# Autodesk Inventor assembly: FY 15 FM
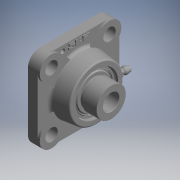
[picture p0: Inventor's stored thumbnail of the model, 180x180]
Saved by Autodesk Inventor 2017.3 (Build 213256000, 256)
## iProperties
Category: PARTsolutions
Company: SKF
Part Number: FY 15 FM
Catalog Web Link: www.cadenas.de
Description: AYF_001HC_HH_HY-Y-bearing square flanged units
Vendor: SKF
Document SubType Name: Assembly
Designer: partserver
Manufacturer: SKF
Mass: 400 g
Surface Area: 332.086 cm^2
Volume: 55.8843 cm^3
Density: 7.15765 g/cm^3
Title: FY 15 FM
Author: Cadenas PARTsolutions
Comments: Y-bearing square flanged units
PSOL_IDENT_0: {$CADENAS_DATA\23d-libs\skf\bearings_units_and_housings\bearing_units\ball_bearing_units\y-units\ayf
PSOL_IDENT_1: _001hc_hh_hy.prj},187 {VTYP=3D},{STYP=ASSTAB},{NB=FY 15 FM},{LINA=FY 15 FM},{NN=AYF_001HC_HH_HY},{DA
PSOL_IDENT_2: TE=20.08.2020 12:22:38},{GEOMDATE=20.08.2020 12:22:32},{VERSION=},{LINEID=52770},{WBVAR=COVER},{WBNU
PSOL_IDENT_3: MERIC=}  {NB=FY 15 FM},{LINA=FY 15 FM},{KT=DUMMY},{DESIGNATION=FY 15 FM},{HOUSING=FY 503 M},{BEARING=
PSOL_IDENT_4: YET 203/15},{COVER=},{DD=15},{DDX=},{DDALG=15.000},{DD1=24.200},{DD2=27.200},{DD3=},{AALG=26.000},{A=
PSOL_IDENT_5: 26},{AX=},{AXX=},{A1ALG=11.000},{A1=11},{A1X=},{A1XX=},{A3ALG=3.200},{A3=3.2},{A3X=},{A5ALG=0.000},{
PSOL_IDENT_6: A5=},{A5X=},{A5XX=},{B=MIN},{B1=28.600},{B1X=},{B4ALG=4.750},{B4=},{B4X=4.75},{DAAALG=55.600},{DAA=5
PSOL_IDENT_7: 5.6},{DAAX=},{DB=MIN},{DB1=50.000},{DB1X=},{DB2=53.000},{DB2X=},{HA=},{J=54.000},{JX=},{JXX=},{L=76.
PSOL_IDENT_8: 000},{LX=},{LXX=},{N=11.500},{NX=},{NXX=},{SS1=22.100},{SS1X=},{T=39.600},{TX=},{DN=6.500},{SWN=7},{
PSOL_IDENT_9: GN=1/4-28 SAE-LT},{RG=1/4-28 UNF},{RGX=},{R1=19},{R1X=},{J6=66},{J7=14.500},{N4=4},{D=40.000},{C=12.
PSOL_IDENT_10: 000},{R12=0.300},{DW=6.747},{B3=13.500},{PITCH=28.500},{LOAD1=9.560},{LOAD2=4.750},{LOAD3=0.200},{SP
PSOL_IDENT_11: EED1=9500},{II=1},{Z=8},{MASS=0.400},{MASSX=},{G2=M6x0.75},{HKSGS=3},{RTTGS=4},{ALPHA=},{GALG=10.000
PSOL_IDENT_12: },{G=10},{GX=},{GXX=},{GINALG=0.375},{GIN=0.375000002475},{GINX=},{GINXX=},{EC=},{BS=},{SLEEVE=},{PO
PSOL_IDENT_13: PULAR=},{D1=MIN},{K=1.3},{CC1=3.6},{BRGTYP=BBY_005},{COVERALG=  '', 'No end cover' },{SUPPRESSED=uns
PSOL_IDENT_14: uppressed},{TC=FY 15 FM},{PPATH=y-bearing_square_flanged_units_parts/ayf_001hc_hh_hy_asmtpl.prj}
NB: FY 15 FM
NN: AYF_001HC_HH_HY
NT: Y-bearing square flanged units
NBSYN: $TC.
LINA: FY 15 FM
CATALOG: SKF
DESIGNATION: FY 15 FM
HOUSING: FY 503 M
BEARING: YET 203/15
COVER: No end cover
DDALG: 15
J: 54
L: 76
T: 39.6
LOAD1: 9.56
LOAD2: 4.75
SPEED1: 9500
SUPPLIER: SKF
ARTICLENO: FY 15 FM
BOMINFO: FY 15 FM
CREATOR: CADENAS GmbH
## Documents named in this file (6)
- e:\temp\worker_102\temp\exporttempdir_144_257_MNU6y\format_0\FY 15 FM.iam
- e:\temp\worker_102\temp\exporttempdir_144_257_MNU6y\format_0\FY 15 FM0_375000002475-dummy.ipt
- e:\temp\worker_102\temp\exporttempdir_144_257_MNU6y\format_0\FY 503 M-housing.ipt
- e:\temp\worker_102\temp\exporttempdir_144_257_MNU6y\format_0\1_4-28 SAE-LT.ipt
- e:\temp\worker_102\temp\exporttempdir_144_257_MNU6y\format_0\YET 203_15-24_21030112021228_6-bearing.ipt
- e:\temp\worker_102\temp\exporttempdir_144_257_MNU6y\format_0\15-40-19_1-12-ybrg2-124-6_747-28_5.ipt
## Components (12 placed, 5 different names)
1. FY 15 FM0_375000002475-dummy:1 — brg_XY@1 <-> housing_XY@2, brg_Z@1 <-> housing_Z@2, brg_YZ@1 <-> housing_YZ@2
2. FY 503 M-housing:1 — brg_XY@1 <-> housing_XY@2, brg_Z@1 <-> housing_Z@2, brg_YZ@1 <-> housing_YZ@2, gn_XY@2 <-> gn_XY@3, gn_Z@2 <-> gn_Z@3, gn_YZ@2 <-> gn_YZ@3, housing_XY@2 <-> brg3_XY@4, housing_Z@2 <-> brg3_Z@4, housing_YZ@2 <-> brg3_YZ@4
3. 1_4-28 SAE-LT:1 — gn_XY@2 <-> gn_XY@3, gn_Z@2 <-> gn_Z@3, gn_YZ@2 <-> gn_YZ@3
4. YET 203_15-24_21030112021228_6-bearing:1 — housing_XY@2 <-> brg3_XY@4, housing_Z@2 <-> brg3_Z@4, housing_YZ@2 <-> brg3_YZ@4, ball_1_XY@4 <-> ball_XY@5, ball_1_Z@4 <-> ball_Z@5, ball_1_YZ@4 <-> ball_YZ@5, ball_2_XY@4 <-> ball_XY@6, ball_2_Z@4 <-> ball_Z@6, ball_2_YZ@4 <-> ball_YZ@6, ball_3_XY@4 <-> ball_XY@7, ball_3_Z@4 <-> ball_Z@7, ball_3_YZ@4 <-> ball_YZ@7, ball_4_XY@4 <-> ball_XY@8, ball_4_Z@4 <-> ball_Z@8, ball_4_YZ@4 <-> ball_YZ@8, ball_5_XY@4 <-> ball_XY@9, ball_5_Z@4 <-> ball_Z@9, ball_5_YZ@4 <-> ball_YZ@9, ball_6_XY@4 <-> ball_XY@10, ball_6_Z@4 <-> ball_Z@10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
5. 15-40-19_1-12-ybrg2-124-6_747-28_5:1 — ball_1_XY@4 <-> ball_XY@5, ball_1_Z@4 <-> ball_Z@5, ball_1_YZ@4 <-> ball_YZ@5
6. 15-40-19_1-12-ybrg2-124-6_747-28_5:2 — ball_2_XY@4 <-> ball_XY@6, ball_2_Z@4 <-> ball_Z@6, ball_2_YZ@4 <-> ball_YZ@6
7. 15-40-19_1-12-ybrg2-124-6_747-28_5:3 — ball_3_XY@4 <-> ball_XY@7, ball_3_Z@4 <-> ball_Z@7, ball_3_YZ@4 <-> ball_YZ@7
8. 15-40-19_1-12-ybrg2-124-6_747-28_5:4 — ball_4_XY@4 <-> ball_XY@8, ball_4_Z@4 <-> ball_Z@8, ball_4_YZ@4 <-> ball_YZ@8
9. 15-40-19_1-12-ybrg2-124-6_747-28_5:5 — ball_5_XY@4 <-> ball_XY@9, ball_5_Z@4 <-> ball_Z@9, ball_5_YZ@4 <-> ball_YZ@9
10. 15-40-19_1-12-ybrg2-124-6_747-28_5:6 — ball_6_XY@4 <-> ball_XY@10, ball_6_Z@4 <-> ball_Z@10, ball_6_YZ@4 <-> ball_YZ@10
11. 15-40-19_1-12-ybrg2-124-6_747-28_5:7 — ball_7_XY@4 <-> ball_XY@11, ball_7_Z@4 <-> ball_Z@11, ball_7_YZ@4 <-> ball_YZ@11
12. 15-40-19_1-12-ybrg2-124-6_747-28_5:8 — ball_8_XY@4 <-> ball_XY@12, ball_8_Z@4 <-> ball_Z@12, ball_8_YZ@4 <-> ball_YZ@12
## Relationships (33: Mate 21, Angle 11, Flush 1)
- brg_XY@1 <-> housing_XY@2 [Mate]: FY 15 FM0_375000002475-dummy:1 ↔ FY 503 M-housing:1
- brg_Z@1 <-> housing_Z@2 [Mate]: FY 15 FM0_375000002475-dummy:1 ↔ FY 503 M-housing:1
- brg_YZ@1 <-> housing_YZ@2 [Angle]: FY 15 FM0_375000002475-dummy:1 ↔ FY 503 M-housing:1
- gn_XY@2 <-> gn_XY@3 [Mate]: FY 503 M-housing:1 ↔ 1_4-28 SAE-LT:1
- gn_Z@2 <-> gn_Z@3 [Mate]: FY 503 M-housing:1 ↔ 1_4-28 SAE-LT:1
- gn_YZ@2 <-> gn_YZ@3 [Angle]: FY 503 M-housing:1 ↔ 1_4-28 SAE-LT:1
- housing_XY@2 <-> brg3_XY@4 [Flush]: FY 503 M-housing:1 ↔ YET 203_15-24_21030112021228_6-bearing:1
- housing_Z@2 <-> brg3_Z@4 [Mate]: FY 503 M-housing:1 ↔ YET 203_15-24_21030112021228_6-bearing:1
- housing_YZ@2 <-> brg3_YZ@4 [Angle]: FY 503 M-housing:1 ↔ YET 203_15-24_21030112021228_6-bearing:1
- ball_1_XY@4 <-> ball_XY@5 [Mate]: YET 203_15-24_21030112021228_6-bearing:1 ↔ 15-40-19_1-12-ybrg2-124-6_747-28_5:1
- ball_1_Z@4 <-> ball_Z@5 [Mate]: YET 203_15-24_21030112021228_6-bearing:1 ↔ 15-40-19_1-12-ybrg2-124-6_747-28_5:1
- ball_1_YZ@4 <-> ball_YZ@5 [Angle]: YET 203_15-24_21030112021228_6-bearing:1 ↔ 15-40-19_1-12-ybrg2-124-6_747-28_5:1
- ball_2_XY@4 <-> ball_XY@6 [Mate]: YET 203_15-24_21030112021228_6-bearing:1 ↔ 15-40-19_1-12-ybrg2-124-6_747-28_5:2
- ball_2_Z@4 <-> ball_Z@6 [Mate]: YET 203_15-24_21030112021228_6-bearing:1 ↔ 15-40-19_1-12-ybrg2-124-6_747-28_5:2
- ball_2_YZ@4 <-> ball_YZ@6 [Angle]: YET 203_15-24_21030112021228_6-bearing:1 ↔ 15-40-19_1-12-ybrg2-124-6_747-28_5:2
- ball_3_XY@4 <-> ball_XY@7 [Mate]: YET 203_15-24_21030112021228_6-bearing:1 ↔ 15-40-19_1-12-ybrg2-124-6_747-28_5:3
- ball_3_Z@4 <-> ball_Z@7 [Mate]: YET 203_15-24_21030112021228_6-bearing:1 ↔ 15-40-19_1-12-ybrg2-124-6_747-28_5:3
- ball_3_YZ@4 <-> ball_YZ@7 [Angle]: YET 203_15-24_21030112021228_6-bearing:1 ↔ 15-40-19_1-12-ybrg2-124-6_747-28_5:3
- ball_4_XY@4 <-> ball_XY@8 [Mate]: YET 203_15-24_21030112021228_6-bearing:1 ↔ 15-40-19_1-12-ybrg2-124-6_747-28_5:4
- ball_4_Z@4 <-> ball_Z@8 [Mate]: YET 203_15-24_21030112021228_6-bearing:1 ↔ 15-40-19_1-12-ybrg2-124-6_747-28_5:4
- ball_4_YZ@4 <-> ball_YZ@8 [Angle]: YET 203_15-24_21030112021228_6-bearing:1 ↔ 15-40-19_1-12-ybrg2-124-6_747-28_5:4
- ball_5_XY@4 <-> ball_XY@9 [Mate]: YET 203_15-24_21030112021228_6-bearing:1 ↔ 15-40-19_1-12-ybrg2-124-6_747-28_5:5
- ball_5_Z@4 <-> ball_Z@9 [Mate]: YET 203_15-24_21030112021228_6-bearing:1 ↔ 15-40-19_1-12-ybrg2-124-6_747-28_5:5
- ball_5_YZ@4 <-> ball_YZ@9 [Angle]: YET 203_15-24_21030112021228_6-bearing:1 ↔ 15-40-19_1-12-ybrg2-124-6_747-28_5:5
- ball_6_XY@4 <-> ball_XY@10 [Mate]: YET 203_15-24_21030112021228_6-bearing:1 ↔ 15-40-19_1-12-ybrg2-124-6_747-28_5:6
- ball_6_Z@4 <-> ball_Z@10 [Mate]: YET 203_15-24_21030112021228_6-bearing:1 ↔ 15-40-19_1-12-ybrg2-124-6_747-28_5:6
- ball_6_YZ@4 <-> ball_YZ@10 [Angle]: YET 203_15-24_21030112021228_6-bearing:1 ↔ 15-40-19_1-12-ybrg2-124-6_747-28_5:6
- ball_7_XY@4 <-> ball_XY@11 [Mate]: YET 203_15-24_21030112021228_6-bearing:1 ↔ 15-40-19_1-12-ybrg2-124-6_747-28_5:7
- ball_7_Z@4 <-> ball_Z@11 [Mate]: YET 203_15-24_21030112021228_6-bearing:1 ↔ 15-40-19_1-12-ybrg2-124-6_747-28_5:7
- ball_7_YZ@4 <-> ball_YZ@11 [Angle]: YET 203_15-24_21030112021228_6-bearing:1 ↔ 15-40-19_1-12-ybrg2-124-6_747-28_5:7
- ball_8_XY@4 <-> ball_XY@12 [Mate]: YET 203_15-24_21030112021228_6-bearing:1 ↔ 15-40-19_1-12-ybrg2-124-6_747-28_5:8
- ball_8_Z@4 <-> ball_Z@12 [Mate]: YET 203_15-24_21030112021228_6-bearing:1 ↔ 15-40-19_1-12-ybrg2-124-6_747-28_5:8
- ball_8_YZ@4 <-> ball_YZ@12 [Angle]: YET 203_15-24_21030112021228_6-bearing:1 ↔ 15-40-19_1-12-ybrg2-124-6_747-28_5:8
